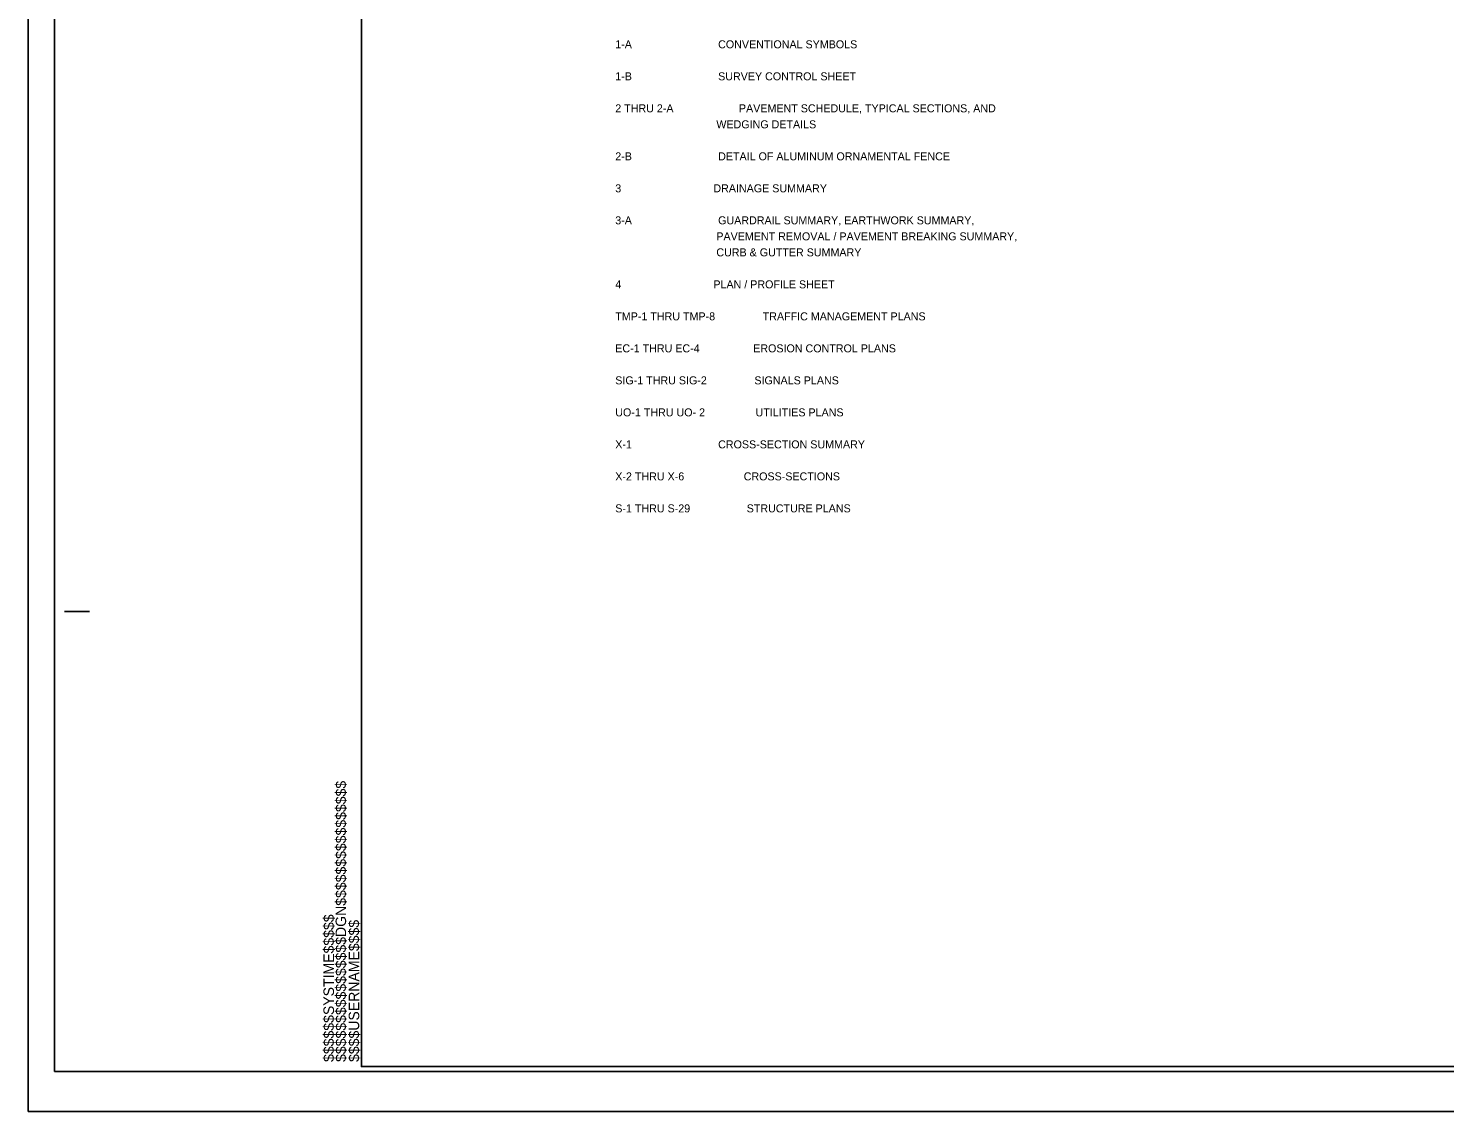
# Model space of a CAD drawing. Extents: x 573851.6 to 573885.3, y -53299.4 to -53277.5.
# Drawn here: x 573851.59 to 573865.75, y -53299.45 to -53288.62 of the extents above; entities that cross this region are included whole.
import ezdxf

# ---------------------------------------------------------------- set-up
doc = ezdxf.new("R2010")
doc.units = 0
for name, color, linetype in [('Old_Level_2', 7, 'Continuous'), ('Old_Level_4', 7, 'Continuous'), ('Sheet Cutting Line CELL', 7, 'Continuous'), ('Sheet Data Text CELL', 7, 'Continuous'), ('Sheet Plot Border Inside CELL', 7, 'Continuous')]:
    doc.layers.add(name, color=color, linetype=linetype)

msp = doc.modelspace()

# ---------------------------------------------------------------- linework, layer by layer
at = {"layer": 'Old_Level_2'}
for p, q in [((573851.95, -53294.449), (573852.2, -53294.449)), ((573854.92, -53298.999), (573854.92, -53298.999))]:
    msp.add_line(p, q, dxfattribs=at)
msp.add_lwpolyline([(573884.92, -53277.999), (573854.92, -53277.999), (573854.92, -53298.999), (573884.92, -53298.999)], close=True, dxfattribs=at)
at = {"layer": 'Old_Level_4'}
msp.add_lwpolyline([(573851.59, -53299.449), (573885.26, -53299.449), (573885.26, -53277.549), (573851.59, -53277.549)], close=True, dxfattribs=at)
at = {"layer": 'Sheet Cutting Line CELL'}
for p, q in [((573851.59, -53277.549), (573851.59, -53299.449)), ((573851.59, -53299.449), (573885.26, -53299.449))]:
    msp.add_line(p, q, dxfattribs=at)
at = {"layer": 'Sheet Plot Border Inside CELL'}
msp.add_lwpolyline([(573851.85, -53299.049), (573885.17, -53299.049), (573885.17, -53277.949), (573851.85, -53277.949)], close=True, dxfattribs=at)

# ---------------------------------------------------------------- texts
at = {"layer": 'Old_Level_2'}
for s, p in [('$$$$$$$$$$$$$$$$DGN$$$$$$$$$$$$$$$$', (573854.767, -53298.952)), ('$$$$$$SYSTIME$$$$$', (573854.646, -53298.952)), ('$$$$USERNAME$$$$', (573854.898, -53298.952))]:
    msp.add_text(s, height=0.105, rotation=90, dxfattribs=at).set_placement(p)
at = {"layer": 'Sheet Data Text CELL'}
for s, p in [('1-A                             CONVENTIONAL SYMBOLS ', (573857.458, -53288.817)), ('1-B                             SURVEY CONTROL SHEET ', (573857.458, -53289.137)), ('2 THRU 2-A                      PAVEMENT SCHEDULE, TYPICAL SECTIONS, AND ', (573857.458, -53289.457)), ('                                  WEDGING DETAILS ', (573857.458, -53289.617)), ('2-B                             DETAIL OF ALUMINUM ORNAMENTAL FENCE', (573857.458, -53289.937)), ('3                               DRAINAGE SUMMARY', (573857.458, -53290.257)), ('3-A                             GUARDRAIL SUMMARY, EARTHWORK SUMMARY,', (573857.458, -53290.577)), ('                                  PAVEMENT REMOVAL / PAVEMENT BREAKING SUMMARY,', (573857.458, -53290.737)), ('                                  CURB & GUTTER SUMMARY ', (573857.458, -53290.897)), ('4                               PLAN / PROFILE SHEET ', (573857.458, -53291.217)), ('TMP-1 THRU TMP-8                TRAFFIC MANAGEMENT PLANS', (573857.458, -53291.537)), ('EC-1 THRU EC-4                  EROSION CONTROL PLANS', (573857.458, -53291.857)), ('SIG-1 THRU SIG-2                SIGNALS PLANS', (573857.458, -53292.177)), ('UO-1 THRU UO- 2                 UTILITIES PLANS', (573857.458, -53292.497)), ('X-1                             CROSS-SECTION SUMMARY', (573857.458, -53292.817)), ('X-2 THRU X-6                    CROSS-SECTIONS', (573857.458, -53293.137)), ('S-1 THRU S-29                   STRUCTURE PLANS', (573857.458, -53293.457))]:
    msp.add_text(s, height=0.08, dxfattribs=at).set_placement(p)

doc.saveas('drawing.dxf')
